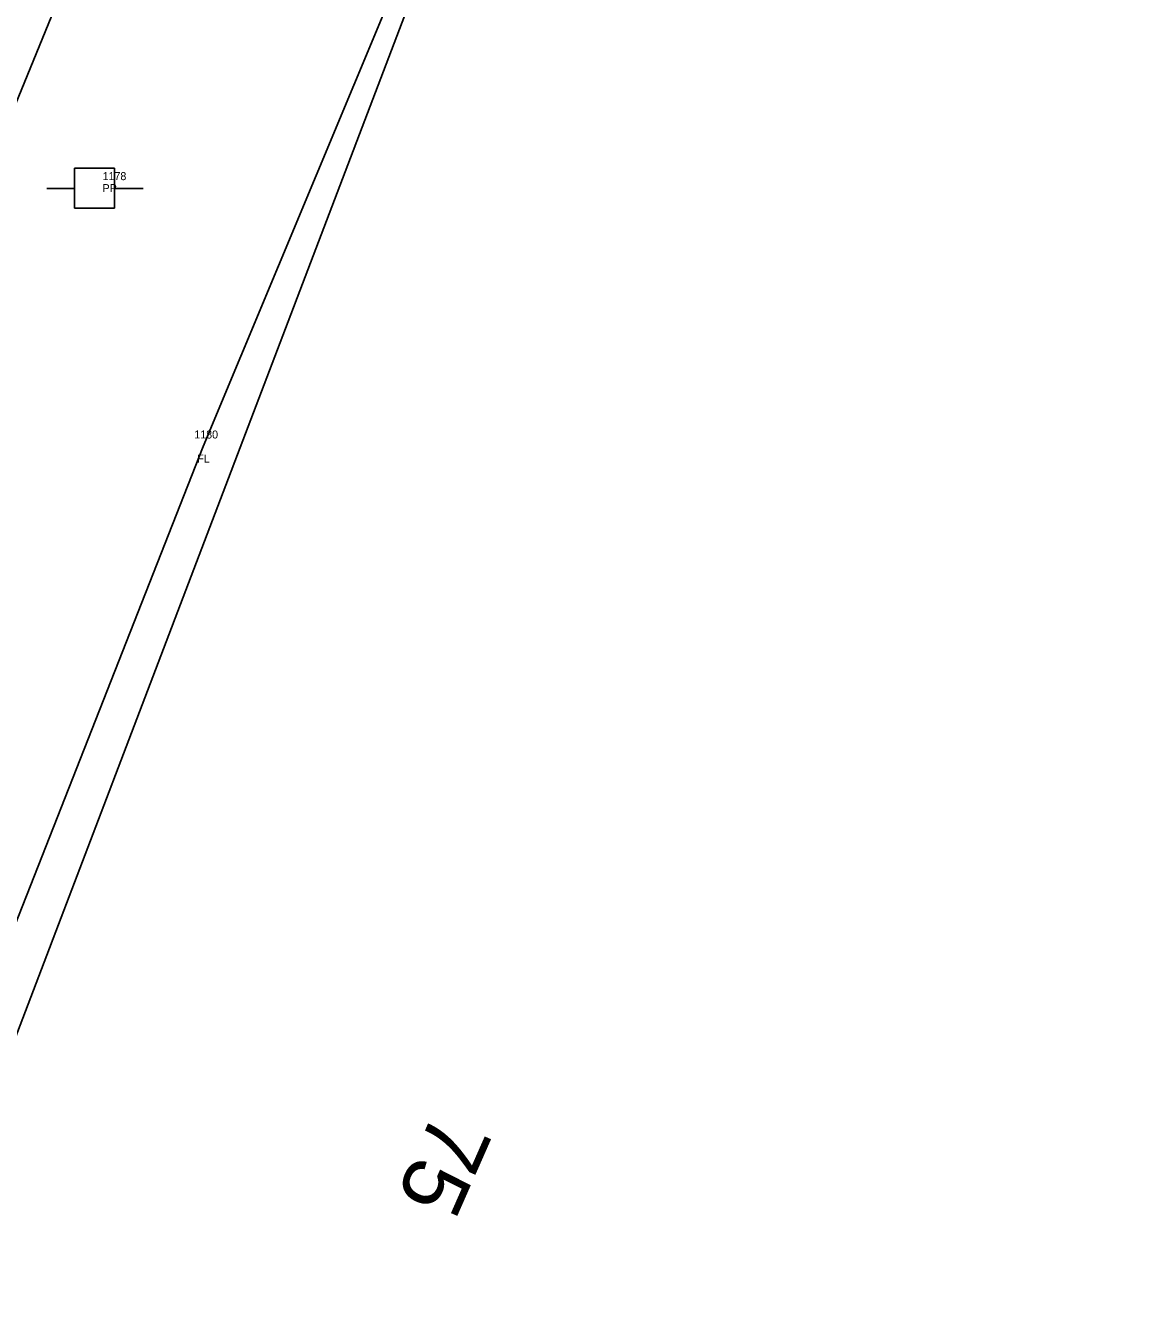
# Model space of a CAD drawing. Extents: x 2432632 to 2433497, y 684847 to 688233.
# Drawn here: x 2432999.3 to 2433137.8, y 685310.2 to 685471.1 of the extents above; entities that cross this region are included whole.
import ezdxf

# ---------------------------------------------------------------- set-up
doc = ezdxf.new("R2010")
doc.units = 0
for name, color, linetype in [('RD_EX_Fence_Other', 7, 'Continuous'), ('RD_EX_Fence_Other_txCode', 7, 'Continuous'), ('RD_EX_Road', 7, 'Continuous'), ('RD_EX_UT', 7, 'Continuous'), ('RD_EX_UT_txCode', 7, 'Continuous'), ('RD_EX_VEG', 7, 'Continuous'), ('RD_HC_TX_Sta50', 7, 'Continuous'), ('RD_SMD_Locator', 7, 'Continuous')]:
    doc.layers.add(name, color=color, linetype=linetype)

msp = doc.modelspace()

# ---------------------------------------------------------------- linework, layer by layer
at = {"layer": 'RD_EX_Fence_Other'}
msp.add_lwpolyline([(2433123.26, 685650.94), (2433063.8, 685520.15), (2433021.44, 685418.51), (2432949, 685234.28), (2432929.52, 685179.08)], dxfattribs=at)
at = {"layer": 'RD_EX_Road'}
msp.add_lwpolyline([(2433077.66, 685687.92), (2433062.23, 685635.7), (2433044.84, 685582.68), (2433028.22, 685537.07), (2433009.68, 685489.83), (2432988.53, 685438.27), (2432948.62, 685345.62), (2432907.86, 685252.74), (2432887.37, 685205.96), (2432872.08, 685170.45), (2432827.85, 685071.69), (2432787.31, 684979.59)], dxfattribs=at)
at = {"layer": 'RD_EX_UT'}
for p, q in [((2433010.37, 685453.3), (2433005.37, 685453.3)), ((2433005.37, 685453.3), (2433005.37, 685448.3)), ((2433010.37, 685448.3), (2433010.37, 685453.3)), ((2433001.94, 685450.74), (2433005.41, 685450.74)), ((2433010.3, 685450.74), (2433013.94, 685450.74)), ((2433005.37, 685448.3), (2433010.37, 685448.3))]:
    msp.add_line(p, q, dxfattribs=at)
at = {"layer": 'RD_EX_VEG'}
msp.add_lwpolyline([(2433137.8, 685665.13), (2433067, 685525.91), (2432991.08, 685326.61), (2432934.15, 685190.44)], dxfattribs=at)
at = {"layer": 'RD_SMD_Locator'}
msp.add_circle((2433021.44, 685418.51), 0.001, dxfattribs=at)

# ---------------------------------------------------------------- texts
at = {"layer": 'RD_EX_Fence_Other_txCode'}
for s, p in [('1180', (2433020.34, 685419.51)), ('FL', (2433020.71, 685416.51))]:
    msp.add_text(s, height=1, dxfattribs=at).set_placement(p)
at = {"layer": 'RD_EX_UT_txCode'}
for s, p in [('1178', (2433008.88, 685451.79)), ('PP', (2433008.88, 685450.29))]:
    msp.add_text(s, height=1, dxfattribs=at).set_placement(p)
at = {"layer": 'RD_HC_TX_Sta50'}
msp.add_text('75', height=8, rotation=246.2329, dxfattribs=at).set_placement((2433050.33, 685335.68))

doc.saveas('drawing.dxf')
